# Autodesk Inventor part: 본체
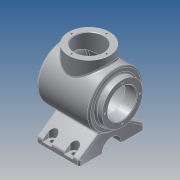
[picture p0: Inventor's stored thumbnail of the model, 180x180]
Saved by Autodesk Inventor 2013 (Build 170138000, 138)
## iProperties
Created: 2017-04
Part Number: 본체
Material: 알루미늄 6061
Document SubType Name: Modeling
Designer: Administrator
Mass: 1670.77 g
Surface Area: 1066.85 cm^2
Volume: 616.519 cm^3
Density: 2.71 g/cm^3
Author: Administrator
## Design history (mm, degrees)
sketch "스케치1"
  geometry: L1 (-48.168, 0)-(59.832, 0); L2 (-48.168, 0)-(-48.168, 50); L3 (-48.168, 50)-(48.168, 50); A1 r 113 centre (-53.168, 0) between (59.832, 0) and (48.168, 50); 5 further points
  constraints: 6 end point, 3 point on line, 2 coincident, 2 horizontal alignment, 2 midpoint, 2 perpendicular, 2 point on circle, 2 vertical alignment, 1 centre point, 1 horizontal
  dimensions: "d0" = 113 radius of A1; "d3" = 108 distance from line of L1.end L2; "d4" = 100 diameter of L3 L1
revolve "회전1" sketch "스케치1" stored, may be unused: angle "d5" = 90 deg
node "작업 평면1"
node "작업 평면2"
sketch "스케치5"
  geometry: C1 r 38 at (0, 0)
  constraints: 1 centre point
  dimensions: "d27" = 76 diameter of C1
extrude "돌출4" join sketch "스케치5" distance "d29" = 12; taper "d30" = 0 deg
node "작업 평면3"
sketch "스케치7"
  geometry: L1 (82, 60)-(82, -60); L2 (82, -60)-(72, -60); L3 (72, -60)-(45.101, -21.584); L4 (82, 60)-(72, 60); L5 (72, 60)-(45.101, 21.584); A1 r 50 centre (0, 0) between (45.101, 21.584) and (45.101, -21.584) reference; 2 further points
  constraints: 10 end point, 2 point on circle, 1 horizontal, 1 horizontal alignment, 1 midpoint, 1 parallel, 1 vertical
  dimensions: "d32" = 120 distance of L1.start L1.end; "d34" = 55 deg angle of L5 L4; "d36" = 55 deg angle of L3 L2; "d38" = 10 distance of L1.start L4.end; "d39" = 10 distance of L1.end L2.end; "d40" = 82 distance from line of L1 point (0, 0)
extrude "돌출5" join sketch "스케치7" distance "d41" = 80; taper "d42" = 0 deg
sketch "스케치8"
  geometry: L1 (-48.168, 50)-(48.168, 50) reference; L2 (-48.168, 50)-(48.168, 50) reference; L3 (-48.168, -50)-(48.168, -50) reference; L4 (-60.168, 38)-(-60.168, -38) reference; L5 (-48.168, 38)-(-60.168, 38) reference; L6 (-48.168, -38)-(-60.168, -38) reference; L7 (-38.168, 40)-(41.748, 40); L8 (-51.924, -40)-(41.748, -40); L9 (49.832, 0)-(-90.051, 0); L10 (-38.168, 40)-(-38.168, 0); A1 r 113 centre (-53.168, 0) between (48.168, -50) and (48.168, 50) reference; A2 r 103 centre (-53.168, 0) between (49.832, 0) and (41.748, 40); 2 further points
  constraints: 8 end point, 3 parallel, 3 point on circle, 2 point on line, 1 centre point, 1 perpendicular
  dimensions: "d45" = 10 radial gap between concentric circles of A2 A1; "d46" = 40 distance between parallel lines of L9 L7; "d47" = 40 distance between parallel lines of L8 L9; "d48" = 22 distance between parallel lines of L10 L4
revolve "회전2" sketch "스케치8" stored, may be unused: angle "d49" = 90 deg
sketch "스케치10"
  geometry: L1 (82, -60)-(82, 60) reference; C1 r 18 at (82, 0); A1 r 50 centre (0, 0) between (45.101, -21.584) and (45.101, 21.584) reference
  constraints: 1 centre point, 1 horizontal alignment, 1 midpoint
  dimensions: "d50" = 36 diameter of C1
extrude "돌출6" cut sketch "스케치10" distance "d52" = 80; taper "d53" = 0 deg
hole "구멍1" diameter "d56" = 54; stored, may be unused: countersink angle "d60" = 90 deg, drill point angle "d62" = 0 deg; dims "d54" = 10, "d55" = 10, "d57" = 6, "d58" = 4, "d59" = 2, "d61" = 22
node "작업 평면4"
sketch "스케치11"
  geometry: L1 (48.168, 50)-(48.168, -50) reference; C1 r 38 at (-1.832, 0); 1 further point
  constraints: 1 centre point, 1 horizontal alignment
  dimensions: "d64" = 76 diameter of C1; "d66" = 50 distance from line of C1.centre L1
extrude "돌출7" join sketch "스케치11" stored distance "d67" = 80; taper "d68" = 0 deg
sketch "스케치13" dims "d71" = 65
  geometry: C1 r 27 at (0, 0) reference; 2 further points
  constraints: 2 vertical alignment, 1 coincident, 2 other
hole "구멍2" sketch "스케치13" at (0, 32.5) diameter "d73" = 3.242; stored, may be unused: countersink angle "d77" = 90 deg, drill point angle "d79" = 118 deg; dims "d74" = 8, "d75" = 4, "d76" = 2, "d78" = 10
sketch "스케치14" dims "d83" = 65
  geometry: C1 r 38 at (0, 0) reference; 3 further points
  constraints: 2 vertical alignment, 1 coincident, 2 other
hole "구멍3" sketch "스케치14" at (0, 32.5) diameter "d85" = 3.242; stored, may be unused: countersink angle "d89" = 90 deg, drill point angle "d91" = 118 deg; dims "d86" = 8, "d87" = 4, "d88" = 2, "d90" = 10
hole "구멍4" diameter "d97" = 54; stored, may be unused: countersink angle "d101" = 90 deg, drill point angle "d103" = 0 deg; dims "d95" = 10, "d96" = 10, "d98" = 8, "d99" = 4, "d100" = 2, "d102" = 59.75
fillet "모깎기1" dims "d104" = 3
chamfer "모따기1" distance "d105" = 1; stored, may be unused: second distance "d106" = 2, angle "d107" = 45 deg
fillet "모깎기2" dims "d108" = 3
fillet "모깎기3" dims "d109" = 3
fillet "모깎기4" dims "d110" = 3
fillet "모깎기5" dims "d111" = 3
fillet "모깎기6" dims "d112" = 3
node "작업 평면5"
sketch "스케치15"
  geometry: L1 (12, 32)-(12, 64.084); L2 (28, 32)-(28, 64.084); L3 (12, 64.084)-(28, 64.084); L4 (3, 42)-(77, 42) reference; L5 (0, 3.271)-(0, 39) reference; L6 (40, 42)-(40, 76.749); L7 (68, 32)-(68, 64.084); L8 (52, 32)-(52, 64.084); L9 (68, 64.084)-(52, 64.084); A1 r 8 centre (20, 32) between (12, 32) and (28, 32); A2 r 8 centre (60, 32) between (52, 32) and (68, 32); 1 further point
  constraints: 14 end point, 5 symmetric about line, 4 point on circle, 2 centre point, 2 parallel, 2 tangent, 1 midpoint, 1 perpendicular, 1 vertical, 1 other
  dimensions: "d114" = 16 distance between parallel lines of L2 L1; "d116" = 10 distance from line of A1.centre L4; "d117" = 20 distance from line of A1.centre L5
extrude "돌출8" cut sketch "스케치15" distance "d118" = 31.75; taper "d119" = 0 deg
extrude "돌출9" cut sketch "스케치15" distance "d120" = 32.5; taper "d121" = 0 deg
hole "구멍5" diameter "d124" = 8; stored, may be unused: countersink angle "d128" = 90 deg, drill point angle "d130" = 0 deg; dims "d122" = 10, "d123" = 10, "d125" = 8, "d126" = 4, "d127" = 2, "d129" = 59.75
hole "구멍6" diameter "d133" = 8; stored, may be unused: countersink angle "d137" = 90 deg, drill point angle "d139" = 0 deg; dims "d131" = 10, "d132" = 10, "d134" = 8, "d135" = 4, "d136" = 2, "d138" = 59.75
node "작업 평면6"
sketch "스케치17"
  geometry: 2 further points
  constraints: 1 coincident, 1 other
feature "엠보싱1" sketch "스케치17" dims "d141" = 0.5, "d142" = 0
node "솔리드1"
pattern_circular "원형 패턴1" dims angle "d81" = 360 deg
pattern_circular "원형 패턴2" dims angle "d93" = 360 deg
mirror "대칭1"
other parameters: "d6" = -82, "d22" = 65, "d31" = -8, "d63" = 65, "d113" = -6, "d140" = -106
